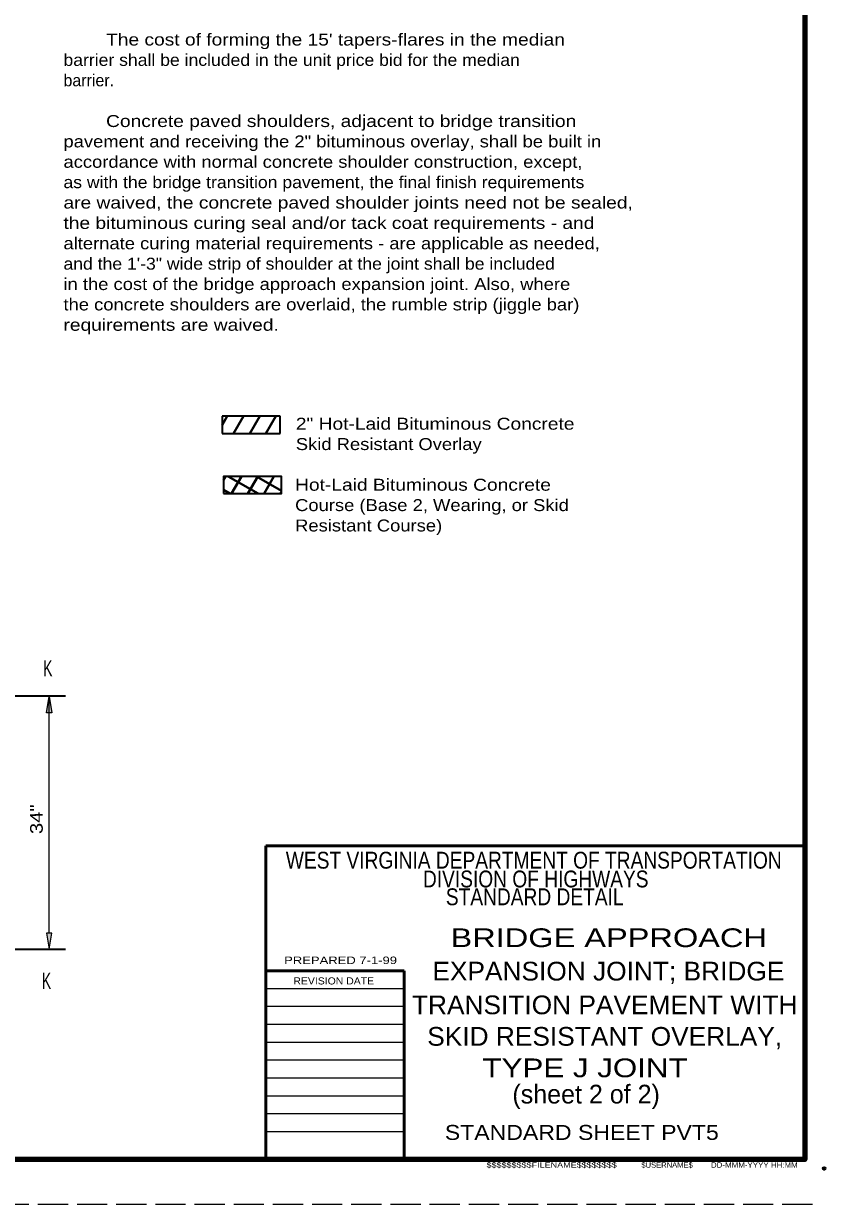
# Model space of a CAD drawing. Extents: x 14 to 49.3, y 28 to 50.
# Drawn here: x 40.4 to 49.32, y 28.04 to 41.18 of the extents above; entities that cross this region are included whole.
import ezdxf
from ezdxf.enums import TextEntityAlignment as Align

# ---------------------------------------------------------------- set-up
doc = ezdxf.new("R2010")
doc.units = 0
doc.header["$LTSCALE"] = 0.056
doc.header["$PDMODE"] = 32
doc.header["$PDSIZE"] = 0.028
doc.linetypes.add('LONG_DASHED', pattern=[7.5, 6, -1.5])
for name, color, linetype, lineweight in [('1', 7, 'Continuous', 35), ('3', 7, 'Continuous', 13), ('5', 7, 'Continuous', 35), ('6', 7, 'Continuous', 13)]:
    doc.layers.add(name, color=color, linetype=linetype, lineweight=lineweight)

msp = doc.modelspace()

# ---------------------------------------------------------------- hatches: boundary and pattern name
at = {"layer": '1'}
for points in [[(40.71358, 33.51225), (40.65358, 33.51225), (40.68358, 33.69225), (40.68358, 33.69225)], [(40.71358, 31.0615), (40.65358, 31.0615), (40.68358, 30.8815), (40.68358, 30.8815)]]:
    msp.add_hatch(color=256, dxfattribs=at).paths.add_polyline_path(points)

# ---------------------------------------------------------------- linework, layer by layer
for p, q in [((42.60742, 36.81008), (42.60742, 36.61917)), ((43.25458, 36.81008), (42.60742, 36.81008)), ((43.25458, 36.61917), (43.25458, 36.81008)), ((42.60742, 36.61917), (43.25458, 36.61917)), ((40.13825, 33.70033), (40.86358, 33.70033)), ((40.13825, 30.8815), (40.86358, 30.8815))]:
    msp.add_line(p, q, dxfattribs=at)
at = {"layer": '1', "lineweight": 40}
for p, q in [((42.60742, 36.71192), (42.66408, 36.81008)), ((42.73433, 36.61917), (42.8445, 36.81008)), ((42.91475, 36.61917), (43.025, 36.81008)), ((43.09517, 36.61917), (43.20542, 36.81008)), ((42.62083, 36.10333), (42.64317, 36.14192)), ((42.67608, 36.14192), (43.00675, 35.951)), ((42.71325, 35.951), (42.82358, 36.14192)), ((42.89367, 35.951), (43.004, 36.14192)), ((42.98858, 36.14192), (43.268, 35.98042)), ((43.07417, 35.951), (43.18442, 36.14192)), ((42.62083, 35.99325), (42.69425, 35.951)), ((43.25458, 35.951), (43.268, 35.97433))]:
    msp.add_line(p, q, dxfattribs=at)
at = {"layer": '1', "lineweight": 25}
for p, q in [((40.68358, 31.0615), (40.68358, 33.70033)), ((44.63117, 30.44292), (43.09325, 30.44292)), ((44.63117, 30.24392), (43.09325, 30.24392)), ((44.63117, 30.04492), (43.09325, 30.04492)), ((44.63117, 29.84592), (43.09325, 29.84592)), ((44.63117, 29.64692), (43.09325, 29.64692)), ((44.63117, 29.44792), (43.09325, 29.44792)), ((44.63117, 29.24892), (43.09325, 29.24892)), ((44.63117, 29.04992), (43.09325, 29.04992)), ((44.63117, 28.85092), (43.09325, 28.85092))]:
    msp.add_line(p, q, dxfattribs=at)
at = {"layer": '1', "lineweight": 53}
for p, q in [((49.09325, 32.03375), (43.09325, 32.03375)), ((43.09325, 28.54392), (43.09325, 32.03375)), ((49.09325, 28.54392), (49.09325, 31.04292)), ((44.63117, 30.64292), (43.09325, 30.64292)), ((44.63117, 28.54392), (44.63117, 30.64292)), ((43.09325, 29.95392), (43.09325, 28.54392)), ((49.09325, 28.54392), (43.09325, 28.54392))]:
    msp.add_line(p, q, dxfattribs=at)
at = {"layer": '1', "linetype": 'LONG_DASHED', "lineweight": 25}
msp.add_line((49.17658, 28.04392), (13.97658, 28.04392), dxfattribs=at)
at = {"layer": '1', "lineweight": 158}
msp.add_lwpolyline([(49.09325, 49.54392), (49.09325, 28.54392), (16.59325, 28.54392)], dxfattribs=at)
at = {"layer": '1'}
msp.add_lwpolyline([(42.62083, 35.951), (43.268, 35.951), (43.268, 36.14192), (42.62083, 36.14192)], close=True, dxfattribs=at)
at = {"layer": '1', "lineweight": 13}
for points in [[(40.71358, 33.51225), (40.65358, 33.51225), (40.68358, 33.69225), (40.68358, 33.69225)], [(40.71358, 31.0615), (40.65358, 31.0615), (40.68358, 30.8815), (40.68358, 30.8815)]]:
    msp.add_lwpolyline(points, close=True, dxfattribs=at)
at = {"layer": '1'}
for p in [(49.09325, 28.54392), (49.30625, 28.44392)]:
    msp.add_point(p, dxfattribs=at)
at = {"layer": '6'}
msp.add_line((40.68358, 30.8815), (40.68367, 30.8815), dxfattribs=at)

# ---------------------------------------------------------------- texts
at = {"layer": '1', "width": 1.2}
msp.add_text('34"', height=0.14, rotation=90.443, dxfattribs=at).set_placement((40.61133, 32.16375))
at = {"layer": '1'}
for s, height, width, p in [('WEST VIRGINIA DEPARTMENT OF TRANSPORTATION', 0.1875, 0.85, (46.075, 31.77883)), ('DIVISION OF HIGHWAYS', 0.1875, 0.85, (46.09687, 31.56992)), ('STANDARD DETAIL', 0.1875, 0.85, (46.08558, 31.37175)), ('     BRIDGE APPROACH    ', 0.2083, 1.3, (46.85887, 30.906)), (' PREPARED 7-1-99', 0.08333, 1.3, (43.90521, 30.7175)), (' EXPANSION JOINT; BRIDGE', 0.2083, 1.05, (46.86446, 30.53442)), ('TRANSITION PAVEMENT WITH', 0.2083, 1.05, (46.86437, 30.15908)), (' SKID RESISTANT OVERLAY, ', 0.2083, 1.05, (46.86442, 29.80875)), ('        TYPE J JOINT        ', 0.2083, 1.25, (46.6455, 29.45842)), ('STANDARD SHEET PVT5      ', 0.1667, 1.15, (46.82342, 28.761))]:
    msp.add_text(s, height=height, dxfattribs=dict(at, width=width)).set_placement(p, align=Align.CENTER)
for s, height, width, p in [('REVISION DATE', 0.079, 1.1, (43.40033, 30.49025)), ('$$$$$$$$$FILENAME$$$$$$$$', 0.06, 1.25, (45.549, 28.45217)), ('$USERNAME$', 0.06, 1.05, (47.27308, 28.45217)), ('DD-MMM-YYYY HH:MM', 0.06, 1.1, (48.04667, 28.45217))]:
    msp.add_text(s, height=height, dxfattribs=dict(at, width=width)).set_placement(p)
msp.add_text('     (sheet 2 of 2)     ', height=0.2083, dxfattribs=at).set_placement((46.65775, 29.16633), align=Align.CENTER)
at = {"layer": '3'}
for s, width, p in [("        The cost of forming the 15' tapers-flares in the median ", 1.2, (40.84158, 40.93492)), ('barrier shall be included in the unit price bid for the median ', 1.1, (40.84158, 40.70825)), ('        Concrete paved shoulders, adjacent to bridge transition ', 1.2, (40.84158, 40.02825)), ('pavement and receiving the 2" bituminous overlay, shall be built in ', 1.15, (40.84158, 39.80158)), ('accordance with normal concrete shoulder construction, except, ', 1.15, (40.84158, 39.57492)), ('as with the bridge transition pavement, the final finish requirements ', 1.1, (40.84158, 39.34825)), ('are waived, the concrete paved shoulder joints need not be sealed, ', 1.2, (40.84158, 39.12158)), ('the bituminous curing seal and/or tack coat requirements - and ', 1.2, (40.84158, 38.89492)), ('alternate curing material requirements - are applicable as needed, ', 1.15, (40.84158, 38.66825)), ('and the 1\'-3" wide strip of shoulder at the joint shall be included ', 1.1, (40.84158, 38.44158)), ('in the cost of the bridge approach expansion joint. Also, where', 1.15, (40.84158, 38.21492)), ('the concrete shoulders are overlaid, the rumble strip (jiggle bar) ', 1.15, (40.84158, 37.98825)), ('requirements are waived.', 1.2, (40.84158, 37.76158)), ('2" Hot-Laid Bituminous Concrete', 1.2, (43.42733, 36.6615)), ('Skid Resistant Overlay', 1.15, (43.42733, 36.43483)), ('Hot-Laid Bituminous Concrete', 1.2, (43.41925, 35.98258)), ('Course (Base 2, Wearing, or Skid', 1.15, (43.41925, 35.75592)), ('Resistant Course)', 1.15, (43.41925, 35.52925))]:
    msp.add_text(s, height=0.133, dxfattribs=dict(at, width=width)).set_placement(p)
msp.add_text('barrier.', height=0.133, dxfattribs=at).set_placement((40.84158, 40.48158))
at = {"layer": '5', "width": 0.65}
for p in [(40.61525, 33.91683), (40.60058, 30.44092)]:
    msp.add_text('K', height=0.18, dxfattribs=at).set_placement(p)

doc.saveas('drawing.dxf')
